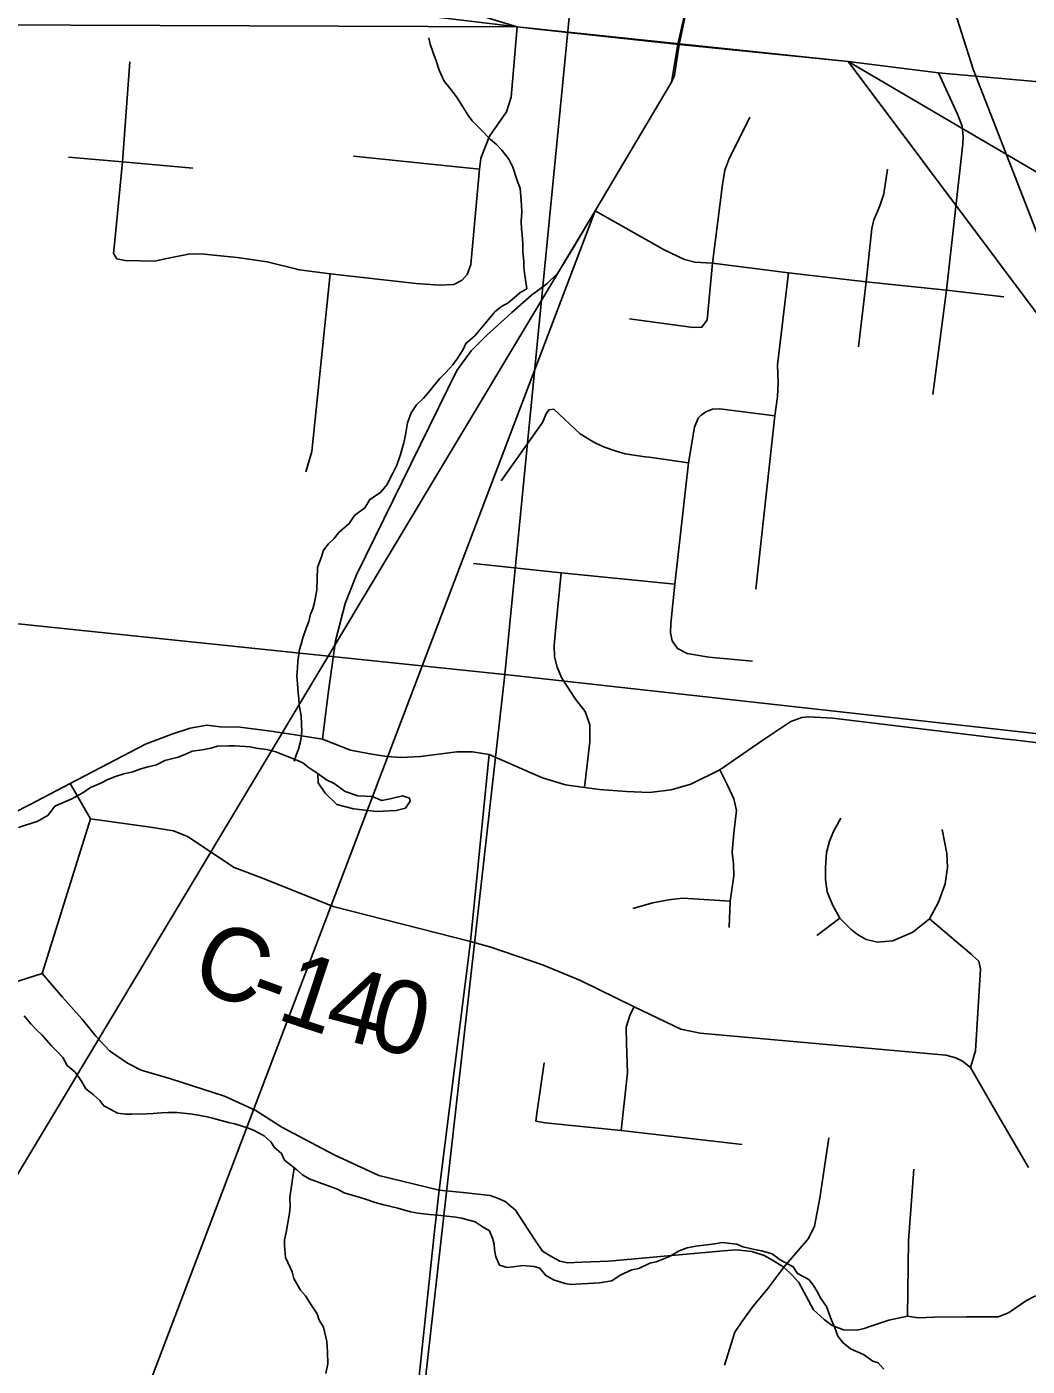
# Model space of a CAD drawing. Extents: x 0 to 43.4, y -8.1 to 22.
# Drawn here: x 6.471 to 7.249, y 17.842 to 18.884 of the extents above; entities that cross this region are included whole.
import ezdxf

# ---------------------------------------------------------------- set-up
doc = ezdxf.new("R2010")
doc.units = 0
for name, color, linetype in [('GM_X_Corporation', 7, 'Continuous'), ('GM_X_County_Road', 7, 'Continuous'), ('GM_X_County_Road_Text', 7, 'Continuous'), ('GM_X_Minor_Lake', 7, 'Continuous'), ('GM_X_Minor_River', 7, 'Continuous'), ('GM_X_Rail_Line', 7, 'Continuous'), ('GM_X_Township_Road', 7, 'Continuous'), ('SH_Text', 7, 'Continuous')]:
    doc.layers.add(name, color=color, linetype=linetype)

msp = doc.modelspace()

# ---------------------------------------------------------------- linework, layer by layer
at = {"layer": 'GM_X_Corporation'}
for points in [[(5.9616, 19.4927), (6.9413, 19.3833), (6.8431, 18.3799), (5.8893, 18.4791)], [(7.955, 19.3167), (7.9506, 19.2736), (7.8526, 18.2674), (6.8431, 18.3799), (6.9413, 19.3833), (7.3067, 19.3445), (7.3077, 19.3879)], [(6.8431, 18.3799), (6.7271, 17.3517), (5.7989, 17.456), (5.8893, 18.4791)], [(6.8431, 18.3799), (7.8526, 18.2674), (7.7575, 17.2431), (6.7271, 17.3517)]]:
    msp.add_lwpolyline(points, close=True, dxfattribs=at)
at = {"layer": 'GM_X_County_Road'}
for points in [[(6.9786, 18.8698), (6.9921, 18.9339), (6.9936, 18.9529)], [(6.2648, 18.9452), (6.2762, 18.9441), (6.4455, 18.9278), (6.51, 18.9216), (6.5147, 18.9212), (6.6008, 18.9124), (6.6536, 18.9063), (6.701, 18.9015), (6.7946, 18.8905), (6.8528, 18.8836), (6.8619, 18.8825)], [(6.8619, 18.8825), (6.8683, 18.8817), (6.9786, 18.8698)], [(6.7012, 18.3294), (6.7057, 18.3651), (6.7115, 18.406), (6.7189, 18.4349), (6.7276, 18.4572), (6.8057, 18.6163), (6.8169, 18.6315), (6.829, 18.6437), (6.8485, 18.6613), (6.8638, 18.6748), (6.8758, 18.6836), (6.884, 18.6917), (6.8964, 18.7118), (6.9134, 18.7404), (6.9727, 18.8404), (6.9751, 18.846), (6.9786, 18.8698)], [(6.9786, 18.8698), (7.1101, 18.8565), (7.1805, 18.8478), (7.2702, 18.8398), (7.3244, 18.8344), (7.3587, 18.8301), (7.3625, 18.8295)], [(6.2495, 18.3271), (6.2636, 18.339), (6.284, 18.3463), (6.3046, 18.3513), (6.319, 18.352), (6.3345, 18.3511), (6.3504, 18.3495), (6.3628, 18.3456), (6.3744, 18.3407), (6.3863, 18.3331), (6.3992, 18.3217), (6.4113, 18.2981), (6.4223, 18.2864), (6.4304, 18.2797), (6.4382, 18.2737), (6.4476, 18.2711), (6.4601, 18.2717), (6.474, 18.2786), (6.5051, 18.295)], [(6.8309, 18.3175), (6.8627, 18.3036), (6.8723, 18.2993), (6.8902, 18.2939), (6.9051, 18.2918), (6.9167, 18.2904), (6.9378, 18.2889), (6.9557, 18.288), (6.9725, 18.29), (6.9877, 18.2946), (7.0104, 18.3055), (7.0431, 18.3283), (7.0656, 18.3432), (7.0741, 18.3463), (7.0794, 18.3469), (7.0983, 18.3459), (7.2329, 18.3296)], [(6.5051, 18.295), (6.5635, 18.3255), (6.584, 18.3333), (6.5984, 18.3381), (6.6113, 18.3403), (6.6216, 18.339), (6.6371, 18.3387), (6.6592, 18.336), (6.6751, 18.3337), (6.7012, 18.3294)], [(6.7012, 18.3294), (6.7231, 18.321), (6.7397, 18.3177), (6.7514, 18.316), (6.7624, 18.3153), (6.7775, 18.316), (6.8058, 18.3197), (6.8179, 18.3196), (6.8309, 18.3175)], [(7.2329, 18.3296), (7.2387, 18.3289), (7.262, 18.326), (7.2766, 18.3243), (7.3541, 18.3158)], [(6.755, 17.6085), (6.7645, 17.6929), (6.7721, 17.7923), (6.7884, 17.9468), (6.7919, 17.9787), (6.8164, 18.1721), (6.8285, 18.2944), (6.8309, 18.3175)], [(6.5051, 18.295), (6.5209, 18.2674), (6.5674, 18.2611), (6.5854, 18.2581), (6.5963, 18.2538), (6.6325, 18.2297), (6.6546, 18.2213), (6.7095, 18.1993), (6.8164, 18.1721), (6.8321, 18.1677), (6.8724, 18.154), (6.902, 18.1419), (6.9436, 18.1212), (6.9801, 18.104), (6.9951, 18.1008), (7.186, 18.0836), (7.1939, 18.0816), (7.1991, 18.079), (7.2053, 18.0741), (7.2249, 18.0398), (7.2504, 17.9963)]]:
    msp.add_lwpolyline(points, dxfattribs=at)
at = {"layer": 'GM_X_Minor_Lake'}
for points in [[(6.6976, 18.3028), (6.6979, 18.2954), (6.7034, 18.2876), (6.7123, 18.2786), (6.7255, 18.2753), (6.7433, 18.2733), (6.7585, 18.274), (6.7658, 18.2757), (6.7694, 18.2813), (6.769, 18.2836), (6.7634, 18.2853), (6.7538, 18.2832)], [(6.7538, 18.2832), (6.7473, 18.2819), (6.7398, 18.2848), (6.7288, 18.2854), (6.719, 18.2887), (6.7104, 18.295), (6.7044, 18.2979), (6.6976, 18.3028)]]:
    msp.add_lwpolyline(points, dxfattribs=at)
at = {"layer": 'GM_X_Minor_River'}
for points in [[(6.8583, 18.692), (6.8578, 18.697), (6.8579, 18.7011), (6.857, 18.7084), (6.8572, 18.7148), (6.8567, 18.7217), (6.8561, 18.7263), (6.8559, 18.7324), (6.8562, 18.7396), (6.856, 18.7449), (6.8555, 18.7518), (6.8549, 18.7579), (6.8525, 18.7648), (6.8494, 18.7744), (6.8462, 18.7806), (6.8408, 18.7876), (6.8364, 18.7923), (6.8319, 18.7959), (6.8242, 18.8038), (6.8176, 18.8105), (6.8144, 18.8152), (6.8104, 18.8214), (6.8054, 18.8292), (6.8003, 18.8358), (6.7959, 18.8413), (6.792, 18.8498), (6.7896, 18.8571), (6.7872, 18.864), (6.7851, 18.8701), (6.784, 18.8749)], [(6.6793, 18.3124), (6.681, 18.3177), (6.6827, 18.3218), (6.6844, 18.3286), (6.6851, 18.3358), (6.6849, 18.3411), (6.6847, 18.3476), (6.6831, 18.356), (6.6829, 18.3609), (6.6823, 18.3655), (6.6818, 18.3724), (6.6812, 18.3785), (6.6818, 18.3849), (6.682, 18.3902), (6.6834, 18.3993), (6.6847, 18.4034), (6.686, 18.4083), (6.6886, 18.4158), (6.6907, 18.4211), (6.692, 18.4267), (6.6937, 18.4309), (6.695, 18.4358), (6.6959, 18.4399), (6.6968, 18.4456), (6.6974, 18.463), (6.7008, 18.4721), (6.7021, 18.4766), (6.706, 18.4814), (6.71, 18.4854), (6.7139, 18.4902), (6.7221, 18.4972), (6.7262, 18.5035), (6.7343, 18.5093), (6.738, 18.516), (6.7465, 18.5214), (6.7513, 18.5273), (6.7558, 18.5359), (6.759, 18.5426), (6.762, 18.5509), (6.7646, 18.5599), (6.7659, 18.5663), (6.7665, 18.5709), (6.7674, 18.5754), (6.7703, 18.5833), (6.7743, 18.5896), (6.7798, 18.5948), (6.7834, 18.5988), (6.7877, 18.604), (6.7925, 18.6099), (6.7972, 18.6147), (6.8027, 18.6206), (6.8059, 18.6254), (6.8107, 18.6325), (6.8128, 18.6373), (6.8198, 18.6432), (6.8262, 18.6509), (6.8357, 18.662), (6.8404, 18.666), (6.8458, 18.6689), (6.8505, 18.6729), (6.8548, 18.6765), (6.8602, 18.6798), (6.8583, 18.692)], [(6.4649, 18.2609), (6.4799, 18.2657), (6.488, 18.2704), (6.4932, 18.2774), (6.5063, 18.283), (6.5148, 18.2877), (6.5207, 18.292), (6.5295, 18.2955), (6.5342, 18.298), (6.5403, 18.3005), (6.5468, 18.3025), (6.5537, 18.3042), (6.5599, 18.3063), (6.5656, 18.308), (6.5721, 18.3096), (6.5787, 18.3128), (6.5891, 18.3155), (6.5956, 18.318), (6.5998, 18.3201), (6.6079, 18.3213), (6.6144, 18.3226), (6.6197, 18.324), (6.6288, 18.3244), (6.633, 18.3243), (6.6451, 18.3235), (6.6493, 18.3226), (6.6576, 18.3215), (6.6651, 18.3197), (6.6741, 18.316), (6.6812, 18.3131), (6.6861, 18.311), (6.6902, 18.3078), (6.6957, 18.3042), (6.6976, 18.3028)], [(6.4693, 18.1144), (6.4744, 18.1081), (6.4788, 18.1034), (6.4829, 18.0995), (6.4906, 18.0909), (6.4946, 18.0869), (6.4994, 18.0818), (6.5026, 18.0756), (6.5088, 18.0705), (6.5139, 18.0634), (6.5171, 18.0576), (6.523, 18.0532), (6.5282, 18.0485), (6.5311, 18.0442), (6.5367, 18.0414), (6.5419, 18.0385), (6.5483, 18.0379), (6.5529, 18.0378), (6.5647, 18.0381), (6.5696, 18.0383), (6.5757, 18.0389), (6.581, 18.0391), (6.5879, 18.0392), (6.5928, 18.0387), (6.5981, 18.0381), (6.6034, 18.0372), (6.6117, 18.0357), (6.6158, 18.0348), (6.6282, 18.0314), (6.6331, 18.0304), (6.6436, 18.027), (6.6481, 18.025), (6.6559, 18.0209), (6.6611, 18.0162), (6.664, 18.0119), (6.6695, 18.0071), (6.6716, 18.0021), (6.6812, 17.9945), (6.6857, 17.9906), (6.6909, 17.9874), (6.7036, 17.9828), (6.713, 17.9794), (6.7182, 17.9765), (6.7306, 17.9731), (6.7355, 17.9714), (6.7422, 17.9692), (6.7479, 17.9675), (6.7599, 17.9648), (6.7697, 17.9618), (6.7754, 17.9609), (6.7844, 17.9598), (6.7909, 17.9592), (6.7981, 17.9586), (6.8049, 17.9576), (6.8094, 17.957), (6.8199, 17.954), (6.8262, 17.95), (6.8311, 17.9472), (6.8335, 17.9414), (6.8349, 17.9368), (6.8351, 17.9322), (6.8361, 17.9268), (6.8389, 17.9203), (6.8449, 17.9186), (6.8495, 17.9192), (6.8571, 17.92), (6.8658, 17.9194), (6.8703, 17.9181), (6.8747, 17.9126), (6.881, 17.9089), (6.89, 17.906), (6.8946, 17.9054), (6.9026, 17.9059), (6.9079, 17.9061), (6.9121, 17.9064), (6.9166, 17.9066), (6.9262, 17.9081), (6.9328, 17.9125), (6.942, 17.9167), (6.9474, 17.9177), (6.9559, 17.9219)], [(6.6792, 17.9962), (6.6759, 17.9731), (6.6761, 17.9655), (6.6755, 17.9609), (6.6731, 17.9458), (6.6718, 17.9401), (6.6716, 17.9356), (6.6724, 17.9264), (6.6777, 17.9152), (6.6791, 17.9099), (6.6841, 17.9009), (6.6881, 17.8966), (6.6924, 17.8896), (6.6971, 17.8826), (6.6988, 17.8776), (6.7021, 17.8722), (6.7047, 17.8611), (6.7052, 17.8527), (6.7053, 17.8436), (6.7039, 17.836)], [(6.9559, 17.9219), (6.9608, 17.9229), (6.9712, 17.9271), (6.9786, 17.9314), (6.9848, 17.9339), (6.9916, 17.9351), (7.0065, 17.9369), (7.0122, 17.9379), (7.0236, 17.9367), (7.0281, 17.9346), (7.0386, 17.9324), (7.0428, 17.9315), (7.0511, 17.9293), (7.0573, 17.9245), (7.0674, 17.9192), (7.0706, 17.9138), (7.0796, 17.9093), (7.0832, 17.9046), (7.0861, 17.8999), (7.089, 17.8945), (7.0933, 17.8883), (7.0954, 17.8825), (7.0971, 17.8775), (7.0996, 17.8725), (7.102, 17.8652), (7.106, 17.8601), (7.1119, 17.8553), (7.122, 17.8508), (7.1294, 17.8456), (7.1335, 17.8443), (7.1379, 17.8396)]]:
    msp.add_lwpolyline(points, dxfattribs=at)
at = {"layer": 'GM_X_Rail_Line'}
msp.add_lwpolyline([(7.2632, 18.7074), (7.2074, 18.8505), (7.1644, 18.9863), (7.1583, 19.0746), (7.1652, 19.1715), (7.1865, 19.2573), (7.219, 19.4133), (7.2179, 19.5252), (7.2022, 19.6149), (7.1807, 19.6909), (7.1291, 19.7994), (7.0756, 19.9038), (7.0435, 19.9755), (6.9966, 20.0582), (6.9615, 20.1077), (6.8485, 20.2259), (6.7559, 20.3339), (6.7119, 20.4011), (6.6759, 20.48), (6.6457, 20.5375), (6.5931, 20.6104)], dxfattribs=at)
at = {"layer": 'GM_X_Township_Road'}
for p, q in [((6.7255, 18.783), (6.8234, 18.7728)), ((6.9553, 18.5488), (6.9859, 18.5444)), ((6.5209, 18.2674), (6.4862, 18.1564)), ((7.0858, 18.1769), (7.1036, 18.1902))]:
    msp.add_line(p, q, dxfattribs=at)
for points in [[(6.8528, 18.8836), (6.848, 18.8289), (6.8445, 18.8173), (6.8311, 18.7986), (6.8245, 18.7813), (6.8234, 18.7728), (6.8166, 18.6987), (6.8137, 18.6908), (6.8098, 18.6866), (6.8035, 18.6832)], [(6.6167, 18.706), (6.6095, 18.7068), (6.6026, 18.707), (6.597, 18.7068), (6.5801, 18.7033), (6.5706, 18.7012), (6.5478, 18.7018), (6.5412, 18.7031), (6.5388, 18.7072), (6.5397, 18.717), (6.5458, 18.7785), (6.5514, 18.8563)], [(7.1761, 18.5976), (7.1865, 18.6786), (7.1993, 18.7926), (7.1997, 18.7983), (7.1987, 18.8063), (7.1952, 18.8157), (7.1805, 18.8478)], [(6.9401, 18.6564), (6.9895, 18.6497), (6.9964, 18.65), (7.0005, 18.6555), (7.0045, 18.6996), (7.0125, 18.7608), (7.0143, 18.772), (7.0173, 18.7804), (7.0336, 18.8132)], [(6.5037, 18.7821), (6.5458, 18.7785), (6.6005, 18.7737)], [(7.1181, 18.6345), (7.1241, 18.6853), (7.1286, 18.7266), (7.13, 18.7333), (7.133, 18.74), (7.1351, 18.7452), (7.1379, 18.7536), (7.1408, 18.7728)], [(6.9134, 18.7404), (6.9671, 18.71), (6.9829, 18.7025), (6.9908, 18.7006), (7.0045, 18.6996), (7.0636, 18.6923), (7.1241, 18.6853), (7.1865, 18.6786), (7.2311, 18.6735)], [(6.8035, 18.6832), (6.7924, 18.6825), (6.7742, 18.6838), (6.7072, 18.6915), (6.6833, 18.6944), (6.6583, 18.7007), (6.635, 18.704), (6.6167, 18.706)], [(6.6883, 18.5373), (6.693, 18.5532), (6.7072, 18.6915)], [(7.0384, 18.4462), (7.0531, 18.5809), (7.0553, 18.596), (7.0557, 18.6063), (7.0551, 18.6205), (7.0636, 18.6923)], [(6.8402, 18.5303), (6.8725, 18.5757), (6.8752, 18.5825), (6.8774, 18.5856), (6.8811, 18.5861), (6.9016, 18.5669), (6.9119, 18.5607), (6.9198, 18.5568), (6.9296, 18.5535), (6.9368, 18.5513), (6.9522, 18.5492), (6.9553, 18.5488)], [(7.0356, 18.3901), (7.0018, 18.3932), (6.9848, 18.396), (6.9774, 18.4001), (6.9732, 18.4059), (6.9719, 18.4121), (6.9721, 18.4195), (6.9754, 18.4501), (6.9859, 18.5444), (6.9907, 18.5722), (6.9935, 18.5792), (6.9958, 18.5816), (6.9995, 18.584), (7.0047, 18.5861), (7.0104, 18.5863), (7.0531, 18.5809)], [(6.8186, 18.466), (6.8868, 18.4589), (6.9754, 18.4501)], [(6.9051, 18.2918), (6.9092, 18.3275), (6.9093, 18.3407), (6.9057, 18.351), (6.898, 18.3606), (6.8873, 18.377), (6.8837, 18.3854), (6.8817, 18.3935), (6.8815, 18.4023), (6.8827, 18.4165), (6.8868, 18.4589)], [(7.0176, 18.1831), (7.0183, 18.2036), (7.0212, 18.2231), (7.021, 18.2326), (7.0199, 18.2417), (7.0211, 18.2565), (7.0234, 18.274), (7.0213, 18.2831), (7.0164, 18.2937), (7.0104, 18.3055)], [(7.1044, 18.268), (7.0989, 18.2582), (7.0957, 18.2502), (7.0932, 18.2414), (7.0924, 18.2297), (7.0924, 18.2204), (7.0938, 18.2107), (7.0982, 18.2001), (7.1036, 18.1902), (7.1122, 18.1818), (7.1173, 18.1775), (7.1242, 18.1736), (7.133, 18.1716), (7.1448, 18.1725), (7.1605, 18.1794), (7.1733, 18.1897), (7.1804, 18.2028), (7.1857, 18.2169), (7.1874, 18.2296), (7.1868, 18.2405), (7.1832, 18.2593)], [(6.9426, 18.1979), (6.9583, 18.2023), (6.9705, 18.2046), (6.9815, 18.2057), (7.0183, 18.2036)], [(7.2071, 18.161), (7.2058, 18.1623), (7.1994, 18.1678), (7.1733, 18.1897)], [(7.2053, 18.0741), (7.2091, 18.0871), (7.2131, 18.1507), (7.2117, 18.1568), (7.2071, 18.161)], [(6.4862, 18.1564), (6.4833, 18.1471), (6.3737, 18.1124), (6.3658, 18.1044), (6.3593, 18.0934), (6.3533, 18.081), (6.3491, 18.0632), (6.3465, 18.0205), (6.3401, 17.991), (6.3274, 17.9601), (6.3202, 17.9478), (6.3028, 17.9248), (6.2796, 17.9075), (6.2637, 17.8903), (6.2547, 17.8804), (6.2537, 17.8775)], [(6.7919, 17.9787), (6.7451, 17.99), (6.7104, 18.0063), (6.6697, 18.0277), (6.6489, 18.041), (6.6251, 18.0517), (6.5833, 18.0654), (6.5602, 18.072), (6.5496, 18.0774), (6.5357, 18.087), (6.5251, 18.0986), (6.5141, 18.1119), (6.4991, 18.1289), (6.4833, 18.1471)], [(6.9436, 18.1212), (6.9407, 18.1154), (6.9374, 18.1055), (6.9378, 18.0927), (6.9386, 18.07), (6.9337, 18.025)], [(6.8738, 18.0777), (6.8679, 18.0384), (6.8673, 18.0324), (6.8744, 18.0312), (6.9337, 18.025), (7.0277, 18.0142)], [(7.0478, 17.9025), (7.0484, 17.9033), (7.06, 17.9188), (7.0793, 17.941), (7.084, 17.9506), (7.0881, 17.9725), (7.0952, 18.0194)], [(7.1562, 17.8807), (7.1571, 17.9392), (7.1611, 17.9951)], [(7.1172, 17.8699), (7.1064, 17.8701), (7.0977, 17.8734), (7.0914, 17.8782), (7.0833, 17.8856), (7.0718, 17.9069), (7.0666, 17.9127), (7.06, 17.9188), (7.0512, 17.9243), (7.0448, 17.9279), (7.0352, 17.9309), (7.0232, 17.9323), (7.0131, 17.9316), (6.924, 17.9235), (6.9029, 17.9226), (6.8919, 17.9222), (6.8859, 17.9235), (6.8784, 17.9276), (6.8724, 17.9312), (6.8675, 17.9385), (6.857, 17.9543), (6.8514, 17.9632), (6.8434, 17.9698), (6.8373, 17.9726), (6.8318, 17.9745), (6.8106, 17.9768), (6.7919, 17.9787)], [(7.014, 17.8427), (7.0221, 17.8683), (7.0279, 17.877), (7.0363, 17.8884), (7.0478, 17.9025)], [(7.289, 17.9061), (7.2608, 17.8979), (7.2549, 17.8959), (7.2489, 17.8928), (7.2348, 17.8834), (7.2269, 17.8803), (7.2023, 17.8802), (7.1774, 17.8799), (7.1646, 17.8795), (7.1562, 17.8807), (7.1418, 17.8776), (7.1316, 17.8742), (7.1271, 17.8727)], [(7.1271, 17.8727), (7.1226, 17.8712), (7.1172, 17.8699)]]:
    msp.add_lwpolyline(points, dxfattribs=at)
at = {"layer": 'SH_Text'}
msp.add_line((6.8528, 18.8836), (7.1101, 18.8565), dxfattribs=at)
for points in [[(5.117, 19.4094), (6.8528, 18.8836), (5.117, 18.89)], [(7.8046, 17.9294), (7.1101, 18.8565), (7.8046, 18.4489)], [(6.3738, 17.8409), (6.9134, 18.7404), (6.3738, 17.3215)]]:
    msp.add_lwpolyline(points, close=True, dxfattribs=at)
msp.add_lwpolyline([(6.9921, 18.9339), (6.9776, 18.8701), (6.9727, 18.8404), (6.9134, 18.7404)], dxfattribs=at)

# ---------------------------------------------------------------- texts
at = {"layer": 'GM_X_County_Road_Text'}
for s, rotation, p in [('C', 338.5772, (6.5963, 18.1382)), ('1', 341.7118, (6.6643, 18.1122)), ('4', 345.175, (6.7009, 18.1002)), ('-', 339.9977, (6.6409, 18.1207)), ('0', 345.7322, (6.735, 18.0912))]:
    msp.add_text(s, height=0.0568, rotation=rotation, dxfattribs=at).set_placement(p)

doc.saveas('drawing.dxf')
